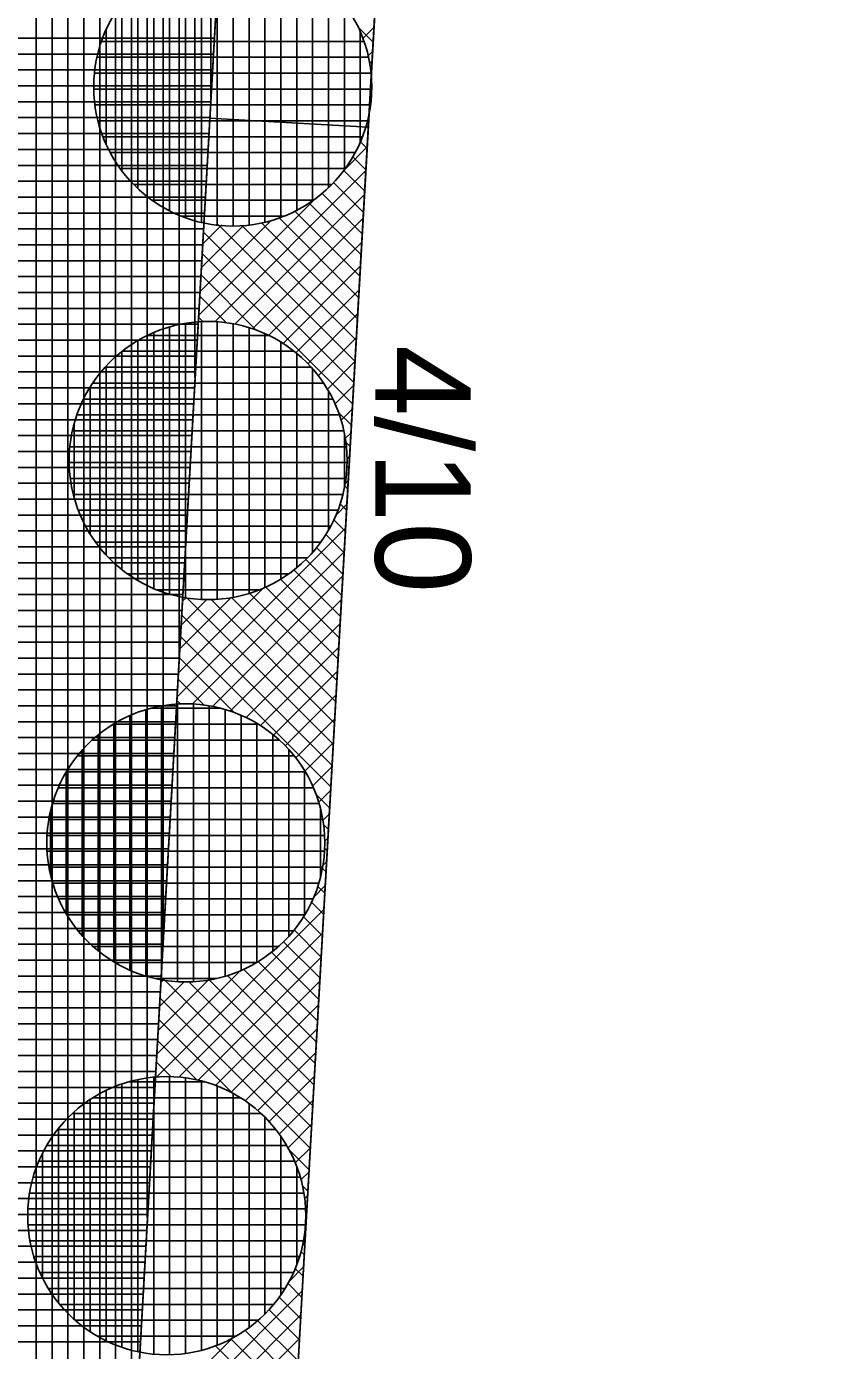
# Model space of a CAD drawing. Extents: x -565346 to -564154, y -1097386 to -1095620.
# Drawn here: x -564270.11 to -564260.14, y -1096822.1 to -1096805.44 of the extents above; entities that cross this region are included whole.
import ezdxf

# ---------------------------------------------------------------- set-up
doc = ezdxf.new("R2010")
doc.units = 0
for name, color, linetype in [('Vrstva 13', 7, 'Continuous'), ('Vrstva 40', 7, 'Continuous'), ('Vrstva 41', 7, 'Continuous'), ('Vrstva 42', 7, 'Continuous'), ('Vrstva 43', 7, 'Continuous'), ('Vrstva 44', 7, 'Continuous')]:
    doc.layers.add(name, color=color, linetype=linetype)

msp = doc.modelspace()

# ---------------------------------------------------------------- linework, layer by layer
at = {"layer": 'Vrstva 13'}
msp.add_line((-564269.4, -1096869.98), (-564261.08, -1096723.43), dxfattribs=at)
at = {"layer": 'Vrstva 41'}
msp.add_line((-564267.806, -1096806.598), (-564265.809, -1096806.711), dxfattribs=at)
msp.add_lwpolyline([(-564261.274, -1096726.84), (-564263.271, -1096726.726), (-564271.397, -1096869.867), (-564273.472, -1096906.437), (-564271.475, -1096906.55), (-564269.4, -1096869.98)], close=True, dxfattribs=at)
at = {"layer": 'Vrstva 42'}
for p, q in [((-564265.933, -1096805.456), (-564265.747, -1096805.642)), ((-564265.737, -1096805.457), (-564265.876, -1096805.596)), ((-564265.754, -1096805.757), (-564265.809, -1096805.813)), ((-564265.796, -1096805.876), (-564265.763, -1096805.91)), ((-564265.771, -1096806.057), (-564265.772, -1096806.058)), ((-564265.805, -1096806.657), (-564265.834, -1096806.686)), ((-564265.834, -1096806.687), (-564265.808, -1096806.713)), ((-564265.822, -1096806.956), (-564266.097, -1096807.232)), ((-564265.907, -1096806.896), (-564265.823, -1096806.98)), ((-564266.002, -1096807.085), (-564265.839, -1096807.248)), ((-564265.839, -1096807.256), (-564267.741, -1096809.159)), ((-564266.115, -1096807.254), (-564265.854, -1096807.515)), ((-564266.246, -1096807.407), (-564265.869, -1096807.783)), ((-564266.486, -1096807.621), (-564267.946, -1096809.081)), ((-564265.856, -1096807.556), (-564267.488, -1096809.188)), ((-564266.553, -1096807.664), (-564265.899, -1096808.318)), ((-564266.391, -1096807.544), (-564265.884, -1096808.051)), ((-564266.733, -1096807.768), (-564265.915, -1096808.586)), ((-564267.032, -1096807.884), (-564267.929, -1096808.781)), ((-564267.378, -1096807.947), (-564267.912, -1096808.481)), ((-564267.653, -1096807.939), (-564267.895, -1096808.181)), ((-564267.697, -1096807.935), (-564265.975, -1096809.657)), ((-564267.401, -1096807.948), (-564265.96, -1096809.389)), ((-564265.873, -1096807.856), (-564267.264, -1096809.247)), ((-564267.15, -1096807.916), (-564265.945, -1096809.121)), ((-564266.931, -1096807.852), (-564265.93, -1096808.854)), ((-564267.886, -1096808.028), (-564265.99, -1096809.924)), ((-564265.89, -1096808.156), (-564267.064, -1096809.33)), ((-564267.902, -1096808.296), (-564266.006, -1096810.192)), ((-564265.907, -1096808.456), (-564266.882, -1096809.431)), ((-564267.917, -1096808.564), (-564267.214, -1096809.266)), ((-564267.932, -1096808.831), (-564267.592, -1096809.172)), ((-564265.924, -1096808.756), (-564266.719, -1096809.55)), ((-564267.947, -1096809.099), (-564267.889, -1096809.158)), ((-564265.941, -1096809.056), (-564266.571, -1096809.686)), ((-564265.958, -1096809.355), (-564266.439, -1096809.837)), ((-564265.975, -1096809.655), (-564266.324, -1096810.004)), ((-564265.992, -1096809.955), (-564266.226, -1096810.189)), ((-564266.186, -1096810.294), (-564266.021, -1096810.46)), ((-564266.009, -1096810.255), (-564266.151, -1096810.397)), ((-564266.026, -1096810.555), (-564266.099, -1096810.627)), ((-564266.092, -1096810.672), (-564266.036, -1096810.727)), ((-564266.078, -1096810.969), (-564266.051, -1096810.995)), ((-564266.043, -1096810.855), (-564266.075, -1096810.886)), ((-564266.06, -1096811.155), (-564266.101, -1096811.195)), ((-564266.105, -1096811.224), (-564266.066, -1096811.263)), ((-564266.077, -1096811.454), (-564266.216, -1096811.594)), ((-564266.162, -1096811.45), (-564266.082, -1096811.53)), ((-564266.243, -1096811.652), (-564266.097, -1096811.798)), ((-564266.094, -1096811.754), (-564268.219, -1096813.879)), ((-564266.344, -1096811.834), (-564266.112, -1096812.065)), ((-564266.462, -1096811.999), (-564266.127, -1096812.333)), ((-564266.111, -1096812.054), (-564268.025, -1096813.968)), ((-564266.596, -1096812.147), (-564266.142, -1096812.601)), ((-564266.746, -1096812.28), (-564266.158, -1096812.868)), ((-564266.128, -1096812.354), (-564267.771, -1096813.997)), ((-564267.097, -1096812.495), (-564266.188, -1096813.404)), ((-564266.913, -1096812.396), (-564266.173, -1096813.136)), ((-564267.134, -1096812.512), (-564268.202, -1096813.579)), ((-564267.533, -1096812.627), (-564268.185, -1096813.279)), ((-564267.841, -1096812.652), (-564268.168, -1096812.979)), ((-564268.097, -1096812.626), (-564268.15, -1096812.679)), ((-564268.098, -1096812.625), (-564266.249, -1096814.474)), ((-564267.788, -1096812.652), (-564266.234, -1096814.207)), ((-564266.145, -1096812.654), (-564267.547, -1096814.056)), ((-564267.531, -1096812.627), (-564266.218, -1096813.939)), ((-564267.302, -1096812.573), (-564266.203, -1096813.671)), ((-564268.16, -1096812.846), (-564266.264, -1096814.742)), ((-564266.162, -1096812.954), (-564267.347, -1096814.138)), ((-564268.175, -1096813.114), (-564266.279, -1096815.01)), ((-564266.18, -1096813.254), (-564267.165, -1096814.239)), ((-564268.19, -1096813.381), (-564267.496, -1096814.075)), ((-564268.206, -1096813.649), (-564267.873, -1096813.981)), ((-564266.197, -1096813.554), (-564267.001, -1096814.358)), ((-564268.221, -1096813.917), (-564268.17, -1096813.968)), ((-564266.214, -1096813.853), (-564266.854, -1096814.493)), ((-564266.231, -1096814.153), (-564266.721, -1096814.644)), ((-564266.248, -1096814.453), (-564266.606, -1096814.811)), ((-564266.265, -1096814.753), (-564266.508, -1096814.996)), ((-564266.465, -1096815.106), (-564266.294, -1096815.277)), ((-564266.282, -1096815.053), (-564266.432, -1096815.203)), ((-564266.299, -1096815.353), (-564266.379, -1096815.433)), ((-564266.371, -1096815.483), (-564266.31, -1096815.545)), ((-564266.316, -1096815.653), (-564266.355, -1096815.692)), ((-564266.358, -1096815.78), (-564266.325, -1096815.813)), ((-564266.333, -1096815.952), (-564266.38, -1096816)), ((-564266.385, -1096816.035), (-564266.34, -1096816.08)), ((-564266.35, -1096816.252), (-564266.494, -1096816.396)), ((-564266.442, -1096816.261), (-564266.355, -1096816.348)), ((-564266.524, -1096816.462), (-564266.37, -1096816.615)), ((-564266.367, -1096816.552), (-564268.476, -1096818.661)), ((-564266.624, -1096816.645), (-564266.386, -1096816.883)), ((-564266.742, -1096816.809), (-564266.401, -1096817.151)), ((-564266.384, -1096816.852), (-564268.194, -1096818.662)), ((-564266.877, -1096816.958), (-564266.416, -1096817.418)), ((-564266.401, -1096817.152), (-564267.949, -1096818.7)), ((-564267.027, -1096817.091), (-564266.431, -1096817.686)), ((-564267.422, -1096817.324), (-564268.474, -1096818.377)), ((-564267.377, -1096817.306), (-564266.462, -1096818.221)), ((-564267.193, -1096817.207), (-564266.446, -1096817.954)), ((-564267.818, -1096817.438), (-564268.457, -1096818.077)), ((-564268.125, -1096817.462), (-564268.44, -1096817.777)), ((-564268.381, -1096817.435), (-564268.423, -1096817.477)), ((-564268.379, -1096817.435), (-564266.522, -1096819.292)), ((-564268.069, -1096817.462), (-564266.507, -1096819.024)), ((-564267.812, -1096817.437), (-564266.492, -1096818.757)), ((-564266.418, -1096817.452), (-564267.733, -1096818.767)), ((-564267.582, -1096817.383), (-564266.477, -1096818.489)), ((-564268.433, -1096817.664), (-564266.538, -1096819.56)), ((-564266.435, -1096817.752), (-564267.537, -1096818.854)), ((-564268.449, -1096817.931), (-564267.516, -1096818.864)), ((-564266.452, -1096818.052), (-564267.359, -1096818.959)), ((-564268.464, -1096818.199), (-564267.967, -1096818.695)), ((-564268.479, -1096818.467), (-564268.289, -1096818.657)), ((-564266.469, -1096818.351), (-564267.2, -1096819.082)), ((-564266.486, -1096818.651), (-564267.056, -1096819.221)), ((-564266.503, -1096818.951), (-564266.928, -1096819.376)), ((-564266.52, -1096819.251), (-564266.818, -1096819.549)), ((-564266.804, -1096819.576), (-564266.553, -1096819.827)), ((-564266.537, -1096819.551), (-564266.727, -1096819.74)), ((-564266.554, -1096819.851), (-564266.656, -1096819.952)), ((-564266.635, -1096820.027), (-564266.568, -1096820.095)), ((-564266.571, -1096820.151), (-564266.609, -1096820.189)), ((-564266.597, -1096820.349), (-564266.583, -1096820.363)), ((-564266.588, -1096820.45), (-564266.597, -1096820.459)), ((-564266.609, -1096820.619), (-564266.598, -1096820.63)), ((-564266.605, -1096820.75), (-564266.635, -1096820.781)), ((-564266.656, -1096820.856), (-564266.613, -1096820.898)), ((-564266.622, -1096821.05), (-564266.804, -1096821.232)), ((-564266.727, -1096821.068), (-564266.629, -1096821.166)), ((-564266.818, -1096821.259), (-564266.644, -1096821.433)), ((-564266.639, -1096821.35), (-564268.737, -1096823.448)), ((-564266.928, -1096821.432), (-564266.659, -1096821.701)), ((-564266.656, -1096821.65), (-564268.463, -1096823.457)), ((-564267.056, -1096821.587), (-564266.674, -1096821.968)), ((-564267.2, -1096821.726), (-564266.689, -1096822.236)), ((-564267.516, -1096821.944), (-564268.746, -1096823.174)), ((-564266.673, -1096821.95), (-564268.226, -1096823.502)), ((-564267.537, -1096821.954), (-564266.72, -1096822.771)), ((-564267.36, -1096821.849), (-564266.705, -1096822.504)), ((-564267.733, -1096822.041), (-564266.735, -1096823.039))]:
    msp.add_line(p, q, dxfattribs=at)
at = {"layer": 'Vrstva 43'}
for p, q in [((-564267.79, -1096806.337), (-564267.79, -1096674.043)), ((-564267.99, -1096809.861), (-564267.99, -1096677.566)), ((-564268.19, -1096813.384), (-564268.19, -1096681.09)), ((-564268.39, -1096816.907), (-564268.39, -1096684.613)), ((-564268.59, -1096820.431), (-564268.59, -1096688.136)), ((-564268.79, -1096823.954), (-564268.79, -1096691.66)), ((-564268.99, -1096827.478), (-564268.99, -1096695.183)), ((-564269.19, -1096831.001), (-564269.19, -1096698.706)), ((-564269.39, -1096834.524), (-564269.39, -1096702.229)), ((-564269.59, -1096838.048), (-564269.59, -1096705.753)), ((-564269.99, -1096845.095), (-564269.99, -1096706.308)), ((-564269.79, -1096841.571), (-564269.79, -1096706.322)), ((-564274.76, -1096805.59), (-564267.748, -1096805.59)), ((-564274.771, -1096805.79), (-564267.759, -1096805.79)), ((-564274.782, -1096805.99), (-564267.77, -1096805.99)), ((-564274.794, -1096806.19), (-564267.782, -1096806.19)), ((-564274.805, -1096806.39), (-564267.793, -1096806.39)), ((-564274.816, -1096806.59), (-564267.804, -1096806.59)), ((-564274.828, -1096806.79), (-564267.816, -1096806.79)), ((-564274.839, -1096806.99), (-564267.827, -1096806.99)), ((-564274.85, -1096807.19), (-564267.838, -1096807.19)), ((-564274.862, -1096807.39), (-564267.85, -1096807.39)), ((-564274.873, -1096807.59), (-564267.861, -1096807.59)), ((-564274.884, -1096807.79), (-564267.872, -1096807.79)), ((-564274.896, -1096807.99), (-564267.884, -1096807.99)), ((-564274.907, -1096808.19), (-564267.895, -1096808.19)), ((-564274.919, -1096808.39), (-564267.907, -1096808.39)), ((-564274.93, -1096808.59), (-564267.918, -1096808.59)), ((-564274.941, -1096808.79), (-564267.929, -1096808.79)), ((-564274.953, -1096808.99), (-564267.941, -1096808.99)), ((-564274.964, -1096809.19), (-564267.952, -1096809.19)), ((-564274.975, -1096809.39), (-564267.963, -1096809.39)), ((-564274.987, -1096809.59), (-564267.975, -1096809.59)), ((-564274.998, -1096809.79), (-564267.986, -1096809.79)), ((-564275.009, -1096809.99), (-564267.997, -1096809.99)), ((-564275.021, -1096810.19), (-564268.009, -1096810.19)), ((-564275.032, -1096810.39), (-564268.02, -1096810.39)), ((-564275.043, -1096810.59), (-564268.031, -1096810.59)), ((-564275.055, -1096810.79), (-564268.043, -1096810.79)), ((-564275.066, -1096810.99), (-564268.054, -1096810.99)), ((-564275.077, -1096811.19), (-564268.065, -1096811.19)), ((-564275.089, -1096811.39), (-564268.077, -1096811.39)), ((-564275.1, -1096811.59), (-564268.088, -1096811.59)), ((-564275.112, -1096811.79), (-564268.1, -1096811.79)), ((-564275.123, -1096811.99), (-564268.111, -1096811.99)), ((-564275.134, -1096812.19), (-564268.122, -1096812.19)), ((-564275.146, -1096812.39), (-564268.134, -1096812.39)), ((-564275.157, -1096812.59), (-564268.145, -1096812.59)), ((-564275.168, -1096812.79), (-564268.156, -1096812.79)), ((-564275.18, -1096812.99), (-564268.168, -1096812.99)), ((-564275.191, -1096813.19), (-564268.179, -1096813.19)), ((-564275.202, -1096813.39), (-564268.19, -1096813.39)), ((-564275.214, -1096813.59), (-564268.202, -1096813.59)), ((-564275.225, -1096813.79), (-564268.213, -1096813.79)), ((-564275.236, -1096813.99), (-564268.224, -1096813.99)), ((-564275.248, -1096814.19), (-564268.236, -1096814.19)), ((-564275.259, -1096814.39), (-564268.247, -1096814.39)), ((-564275.271, -1096814.59), (-564268.258, -1096814.59)), ((-564275.282, -1096814.79), (-564268.27, -1096814.79)), ((-564275.293, -1096814.99), (-564268.281, -1096814.99)), ((-564275.305, -1096815.19), (-564268.293, -1096815.19)), ((-564275.316, -1096815.39), (-564268.304, -1096815.39)), ((-564275.327, -1096815.59), (-564268.315, -1096815.59)), ((-564275.339, -1096815.79), (-564268.327, -1096815.79)), ((-564275.35, -1096815.99), (-564268.338, -1096815.99)), ((-564275.361, -1096816.19), (-564268.349, -1096816.19)), ((-564275.373, -1096816.39), (-564268.361, -1096816.39)), ((-564275.384, -1096816.59), (-564268.372, -1096816.59)), ((-564275.395, -1096816.79), (-564268.383, -1096816.79)), ((-564275.407, -1096816.99), (-564268.395, -1096816.99)), ((-564275.418, -1096817.19), (-564268.406, -1096817.19)), ((-564275.429, -1096817.39), (-564268.417, -1096817.39)), ((-564275.441, -1096817.59), (-564268.429, -1096817.59)), ((-564275.452, -1096817.79), (-564268.44, -1096817.79)), ((-564275.464, -1096817.99), (-564268.451, -1096817.99)), ((-564275.475, -1096818.19), (-564268.463, -1096818.19)), ((-564275.486, -1096818.39), (-564268.474, -1096818.39)), ((-564275.498, -1096818.59), (-564268.486, -1096818.59)), ((-564275.509, -1096818.79), (-564268.497, -1096818.79)), ((-564275.52, -1096818.99), (-564268.508, -1096818.99)), ((-564275.532, -1096819.19), (-564268.52, -1096819.19)), ((-564275.543, -1096819.39), (-564268.531, -1096819.39)), ((-564275.554, -1096819.59), (-564268.542, -1096819.59)), ((-564275.566, -1096819.79), (-564268.554, -1096819.79)), ((-564275.577, -1096819.99), (-564268.565, -1096819.99)), ((-564275.588, -1096820.19), (-564268.576, -1096820.19)), ((-564275.6, -1096820.39), (-564268.588, -1096820.39)), ((-564275.611, -1096820.59), (-564268.599, -1096820.59)), ((-564275.622, -1096820.79), (-564268.61, -1096820.79)), ((-564275.634, -1096820.99), (-564268.622, -1096820.99)), ((-564275.645, -1096821.19), (-564268.633, -1096821.19)), ((-564275.657, -1096821.39), (-564268.644, -1096821.39)), ((-564275.668, -1096821.59), (-564268.656, -1096821.59)), ((-564275.679, -1096821.79), (-564268.667, -1096821.79)), ((-564275.691, -1096821.99), (-564268.679, -1096821.99))]:
    msp.add_line(p, q, dxfattribs=at)
msp.add_lwpolyline([(-564272.899, -1096931.51), (-564271.475, -1096906.55), (-564273.472, -1096906.437), (-564263.271, -1096726.726), (-564261.274, -1096726.84), (-564260.141, -1096706.872)], dxfattribs=at)
at = {"layer": 'Vrstva 44'}
for p, q in [((-564267.91, -1096804.501), (-564267.91, -1096807.908)), ((-564267.71, -1096804.467), (-564267.71, -1096807.942)), ((-564267.51, -1096804.455), (-564267.51, -1096807.952)), ((-564267.31, -1096804.467), (-564267.31, -1096807.94)), ((-564267.11, -1096804.503), (-564267.11, -1096807.905)), ((-564268.31, -1096804.646), (-564268.31, -1096807.762)), ((-564268.11, -1096804.56), (-564268.11, -1096807.848)), ((-564266.91, -1096804.564), (-564266.91, -1096807.846)), ((-564266.71, -1096804.651), (-564266.71, -1096807.756)), ((-564268.51, -1096804.767), (-564268.51, -1096807.641)), ((-564266.51, -1096804.773), (-564266.51, -1096807.635)), ((-564268.71, -1096804.926), (-564268.71, -1096807.481)), ((-564266.31, -1096804.936), (-564266.31, -1096807.471)), ((-564268.91, -1096805.15), (-564268.91, -1096807.257)), ((-564266.11, -1096805.163), (-564266.11, -1096807.247)), ((-564269.11, -1096805.488), (-564269.11, -1096806.923)), ((-564265.91, -1096805.506), (-564265.91, -1096806.898)), ((-564269.167, -1096805.63), (-564265.863, -1096805.63)), ((-564269.222, -1096805.83), (-564265.805, -1096805.83)), ((-564269.254, -1096806.03), (-564265.775, -1096806.03)), ((-564269.263, -1096806.23), (-564265.767, -1096806.23)), ((-564269.249, -1096806.43), (-564265.781, -1096806.43)), ((-564269.211, -1096806.63), (-564265.818, -1096806.63)), ((-564269.147, -1096806.83), (-564265.881, -1096806.83)), ((-564269.056, -1096807.03), (-564265.974, -1096807.03)), ((-564268.931, -1096807.23), (-564266.098, -1096807.23)), ((-564268.761, -1096807.43), (-564266.268, -1096807.43)), ((-564268.526, -1096807.63), (-564266.503, -1096807.63)), ((-564268.161, -1096807.83), (-564266.871, -1096807.83)), ((-564267.91, -1096809.158), (-564267.91, -1096812.651)), ((-564267.71, -1096809.16), (-564267.71, -1096812.65)), ((-564268.587, -1096809.33), (-564267.064, -1096809.33)), ((-564268.51, -1096809.296), (-564268.51, -1096812.513)), ((-564268.31, -1096809.223), (-564268.31, -1096812.585)), ((-564268.11, -1096809.178), (-564268.11, -1096812.629)), ((-564267.51, -1096809.184), (-564267.51, -1096812.624)), ((-564267.31, -1096809.232), (-564267.31, -1096812.575)), ((-564267.11, -1096809.308), (-564267.11, -1096812.5)), ((-564268.71, -1096809.396), (-564268.71, -1096812.411)), ((-564266.91, -1096809.414), (-564266.91, -1096812.396)), ((-564268.91, -1096809.533), (-564268.91, -1096812.277)), ((-564268.907, -1096809.53), (-564266.743, -1096809.53)), ((-564266.71, -1096809.556), (-564266.71, -1096812.251)), ((-564269.121, -1096809.73), (-564266.529, -1096809.73)), ((-564269.11, -1096809.719), (-564269.11, -1096812.089)), ((-564266.51, -1096809.751), (-564266.51, -1096812.057)), ((-564269.31, -1096809.982), (-564269.31, -1096811.826)), ((-564269.276, -1096809.93), (-564266.372, -1096809.93)), ((-564269.393, -1096810.13), (-564266.257, -1096810.13)), ((-564266.31, -1096810.03), (-564266.31, -1096811.778)), ((-564269.477, -1096810.33), (-564266.173, -1096810.33)), ((-564269.51, -1096810.439), (-564269.51, -1096811.368)), ((-564269.532, -1096810.53), (-564266.115, -1096810.53)), ((-564266.11, -1096810.56), (-564266.11, -1096811.245)), ((-564269.564, -1096810.73), (-564266.085, -1096810.73)), ((-564269.573, -1096810.93), (-564266.077, -1096810.93)), ((-564269.559, -1096811.13), (-564266.091, -1096811.13)), ((-564269.521, -1096811.33), (-564266.128, -1096811.33)), ((-564269.457, -1096811.53), (-564266.191, -1096811.53)), ((-564269.366, -1096811.73), (-564266.284, -1096811.73)), ((-564269.241, -1096811.93), (-564266.408, -1096811.93)), ((-564269.071, -1096812.13), (-564266.578, -1096812.13)), ((-564268.836, -1096812.33), (-564266.813, -1096812.33)), ((-564268.471, -1096812.53), (-564267.181, -1096812.53)), ((-564268.41, -1096813.991), (-564268.41, -1096817.435)), ((-564268.21, -1096813.969), (-564268.21, -1096817.459)), ((-564268.01, -1096813.969), (-564268.01, -1096817.46)), ((-564267.81, -1096813.991), (-564267.81, -1096817.438)), ((-564268.81, -1096814.114), (-564268.81, -1096817.314)), ((-564268.61, -1096814.04), (-564268.61, -1096817.389)), ((-564268.539, -1096814.02), (-564267.675, -1096814.02)), ((-564267.61, -1096814.037), (-564267.61, -1096817.391)), ((-564267.41, -1096814.109), (-564267.41, -1096817.318)), ((-564269.015, -1096814.22), (-564267.198, -1096814.22)), ((-564269.01, -1096814.217), (-564269.01, -1096817.21)), ((-564267.21, -1096814.213), (-564267.21, -1096817.217)), ((-564269.282, -1096814.42), (-564266.93, -1096814.42)), ((-564269.21, -1096814.359), (-564269.21, -1096817.07)), ((-564267.01, -1096814.35), (-564267.01, -1096817.076)), ((-564269.469, -1096814.62), (-564266.741, -1096814.62)), ((-564269.41, -1096814.548), (-564269.41, -1096816.879)), ((-564266.81, -1096814.541), (-564266.81, -1096816.89)), ((-564269.61, -1096814.82), (-564266.603, -1096814.82)), ((-564269.61, -1096814.821), (-564269.61, -1096816.606)), ((-564266.61, -1096814.809), (-564266.61, -1096816.623)), ((-564269.71, -1096815.02), (-564266.499, -1096815.02)), ((-564269.81, -1096815.323), (-564269.81, -1096816.109)), ((-564269.782, -1096815.22), (-564266.428, -1096815.22)), ((-564266.41, -1096815.288), (-564266.41, -1096816.143)), ((-564269.829, -1096815.42), (-564266.382, -1096815.42)), ((-564269.853, -1096815.62), (-564266.36, -1096815.62)), ((-564269.851, -1096815.82), (-564266.359, -1096815.82)), ((-564269.827, -1096816.02), (-564266.383, -1096816.02)), ((-564269.779, -1096816.22), (-564266.432, -1096816.22)), ((-564269.706, -1096816.42), (-564266.506, -1096816.42)), ((-564269.601, -1096816.62), (-564266.609, -1096816.62)), ((-564269.46, -1096816.82), (-564266.752, -1096816.82)), ((-564269.268, -1096817.02), (-564266.942, -1096817.02)), ((-564268.993, -1096817.22), (-564267.216, -1096817.22)), ((-564268.495, -1096817.42), (-564267.724, -1096817.42)), ((-564268.51, -1096818.663), (-564268.51, -1096822.145)), ((-564268.31, -1096818.655), (-564268.31, -1096822.152)), ((-564269.11, -1096818.831), (-564269.11, -1096821.977)), ((-564268.91, -1096818.75), (-564268.91, -1096822.058)), ((-564268.821, -1096818.72), (-564267.876, -1096818.72)), ((-564268.71, -1096818.694), (-564268.71, -1096822.115)), ((-564268.11, -1096818.672), (-564268.11, -1096822.136)), ((-564267.91, -1096818.711), (-564267.91, -1096822.098)), ((-564267.71, -1096818.775), (-564267.71, -1096822.033)), ((-564269.31, -1096818.946), (-564269.31, -1096821.863)), ((-564269.273, -1096818.92), (-564267.422, -1096818.92)), ((-564267.51, -1096818.867), (-564267.51, -1096821.939)), ((-564267.31, -1096818.996), (-564267.31, -1096821.814)), ((-564269.534, -1096819.12), (-564267.159, -1096819.12)), ((-564269.51, -1096819.099), (-564269.51, -1096821.708)), ((-564267.11, -1096819.165), (-564267.11, -1096821.64)), ((-564269.717, -1096819.32), (-564266.974, -1096819.32)), ((-564269.71, -1096819.311), (-564269.71, -1096821.497)), ((-564266.91, -1096819.404), (-564266.91, -1096821.401)), ((-564269.91, -1096819.623), (-564269.91, -1096821.184)), ((-564269.856, -1096819.52), (-564266.837, -1096819.52)), ((-564269.954, -1096819.72), (-564266.736, -1096819.72)), ((-564266.71, -1096819.788), (-564266.71, -1096821.025)), ((-564270.025, -1096819.92), (-564266.666, -1096819.92)), ((-564270.072, -1096820.12), (-564266.621, -1096820.12)), ((-564270.093, -1096820.32), (-564266.599, -1096820.32)), ((-564270.09, -1096820.52), (-564266.6, -1096820.52)), ((-564270.065, -1096820.72), (-564266.626, -1096820.72)), ((-564270.016, -1096820.92), (-564266.676, -1096820.92)), ((-564269.942, -1096821.12), (-564266.751, -1096821.12)), ((-564269.835, -1096821.32), (-564266.855, -1096821.32)), ((-564269.692, -1096821.52), (-564267, -1096821.52)), ((-564269.496, -1096821.72), (-564267.194, -1096821.72)), ((-564269.216, -1096821.92), (-564267.474, -1096821.92))]:
    msp.add_line(p, q, dxfattribs=at)
for centre in [(-564267.515, -1096806.204), (-564267.825, -1096810.904), (-564268.106, -1096815.714), (-564268.346, -1096820.404)]:
    msp.add_circle(centre, 1.75, dxfattribs=at)

# ---------------------------------------------------------------- texts
at = {"layer": 'Vrstva 40'}
msp.add_text('4/10', height=1.2, rotation=270, dxfattribs=at).set_placement((-564265.72, -1096809.45))

doc.saveas('drawing.dxf')
